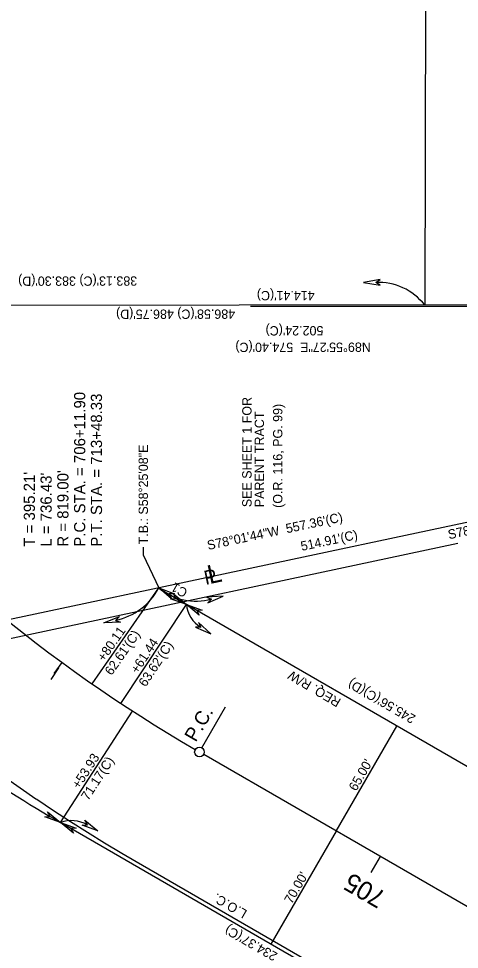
# Model space of a CAD drawing. Extents: x 2003883 to 2008298, y 399149 to 424047.
# Drawn here: x 2006208 to 2006444.4, y 402845.4 to 403344.2 of the extents above; entities that cross this region are included whole.
import ezdxf

# ---------------------------------------------------------------- set-up
doc = ezdxf.new("R2010")
doc.units = 0
for name, color, linetype in [('BaselineSurvey', 7, 'Continuous'), ('BaselineTextWt1', 7, 'Continuous'), ('BaselineTextWt2', 7, 'Continuous'), ('ConstLimits', 7, 'Continuous'), ('ConstLimitsText', 7, 'Continuous'), ('EaseLine_ep', 7, 'Continuous'), ('PropertyLine_ep', 7, 'Continuous'), ('PropertyLineSymbol_ep', 7, 'Continuous'), ('PropertyLineText_ep', 7, 'Continuous'), ('RWandLA_StaTie', 7, 'Continuous'), ('RWandLA_Text', 7, 'Continuous'), ('RWandLA_WidthArrow', 7, 'Continuous'), ('RWLine', 7, 'Continuous')]:
    doc.layers.add(name, color=color, linetype=linetype)

msp = doc.modelspace()

# ---------------------------------------------------------------- linework, layer by layer
at = {"layer": 'BaselineSurvey'}
for p, q in [((2006231.22, 402999.2), (2006226.79, 402993.14)), ((2006229.38, 402996.29), (2006225.24, 402990.04)), ((2006229.38, 402996.29), (2006225.24, 402990.04)), ((2006832.62, 402646.39), (2006307.25, 402949.82)), ((2006401.9, 402895.16), (2006396.89, 402886.5))]:
    msp.add_line(p, q, dxfattribs=at)
msp.add_circle((2006305, 402951.12), 2.6, dxfattribs=at)
msp.add_arc((2006714.61, 403660.33), 819, 220.6437, 239.80922, dxfattribs=at)
at = {"layer": 'BaselineTextWt2'}
msp.add_line((2006306.3, 402953.37), (2006318.98, 402975.33), dxfattribs=at)
at = {"layer": 'ConstLimits'}
for points in [[(2006479.85, 403190), (2006332.39, 403189.92)], [(2006560.75, 402724.93), (2006271.01, 402892.27), (2006263.43, 402896.7), (2006254.14, 402902.26), (2006244.92, 402907.94), (2006235.77, 402913.73), (2006226.69, 402919.64), (2006217.68, 402925.65), (2006217.32, 402925.89), (2006217.23, 402925.95), (2006208.75, 402931.77), (2006199.89, 402938), (2006191.11, 402944.34), (2006182.4, 402950.79), (2006173.78, 402957.34), (2006165.23, 402963.99), (2006156.77, 402970.75), (2006148.39, 402977.62), (2006144.25, 402981.1)]]:
    msp.add_lwpolyline(points, dxfattribs=at)
at = {"layer": 'EaseLine_ep'}
msp.add_line((2006443.58, 403062.83), (2006135.87, 402997.59), dxfattribs=at)
at = {"layer": 'PropertyLine_ep'}
for p, q in [((2006426.99, 403705.03), (2006425.79, 403190.74)), ((2006629, 403112.41), (2006166.22, 403014.29))]:
    msp.add_line(p, q, dxfattribs=at)
at = {"layer": 'PropertyLineText_ep'}
for p, q in [((2006401.92, 403204.31), (2006393.02, 403202.81)), ((2006393.05, 403202.82), (2006401.95, 403201.27)), ((2006399.55, 403202.82), (2006401.95, 403204.32)), ((2006401.95, 403201.27), (2006399.55, 403202.82)), ((2006317.75, 403034.6), (2006308.73, 403034.13)), ((2006308.73, 403034.13), (2006311.41, 403033.15)), ((2006311.41, 403033.15), (2006309.41, 403031.15)), ((2006309.43, 403031.17), (2006317.77, 403034.62)), ((2006253.69, 403020.36), (2006262.02, 403023.74)), ((2006262.02, 403023.74), (2006260, 403021.72)), ((2006260, 403021.72), (2006262.67, 403020.71)), ((2006262.67, 403020.71), (2006253.69, 403020.36))]:
    msp.add_line(p, q, dxfattribs=at)
for centre, radius, start, end in [((2006400.86, 403171.13), 31.72, 38.1943, 92.3877), ((2006253.03, 403055.12), 34.11, 281.8454, 331.9543), ((2006303.07, 403063.76), 31.72, 231.0711, 285.2644)]:
    msp.add_arc(centre, radius, start, end, dxfattribs=at)
at = {"layer": 'RWandLA_StaTie'}
for p, q in [((2006247.42, 402987.65), (2006283.14, 403039.08)), ((2006262.88, 402977.18), (2006297.96, 403030.25)), ((2006230.45, 402913.34), (2006269.16, 402973.07))]:
    msp.add_line(p, q, dxfattribs=at)
at = {"layer": 'RWandLA_Text'}
for p, q in [((2006290.03, 403033.31), (2006283.14, 403039.08)), ((2006283.14, 403039.08), (2006291.58, 403036)), ((2006291.58, 403036), (2006288.72, 403035.86)), ((2006288.72, 403035.86), (2006290.03, 403033.31)), ((2006289.53, 403033.33), (2006292.38, 403033.47)), ((2006297.96, 403030.25), (2006289.53, 403033.33)), ((2006291.08, 403036.01), (2006297.96, 403030.25)), ((2006292.38, 403033.47), (2006291.08, 403036.01)), ((2006304.85, 403024.48), (2006297.96, 403030.25)), ((2006297.96, 403030.25), (2006306.4, 403027.16)), ((2006306.4, 403027.16), (2006303.55, 403027.02)), ((2006303.55, 403027.02), (2006304.85, 403024.48)), ((2006305.64, 403018.03), (2006302.81, 403018.08)), ((2006302.83, 403018.08), (2006311.11, 403014.47)), ((2006311.08, 403014.48), (2006304.47, 403020.63)), ((2006304.47, 403020.63), (2006305.64, 403018.03)), ((2006223.56, 402919.11), (2006230.45, 402913.34)), ((2006224.86, 402916.57), (2006223.56, 402919.11)), ((2006222.01, 402916.43), (2006224.86, 402916.57)), ((2006230.45, 402913.34), (2006222.01, 402916.43)), ((2006237.34, 402907.57), (2006230.45, 402913.34)), ((2006230.45, 402913.34), (2006238.89, 402910.26)), ((2006242.06, 402911.93), (2006244.91, 402912.09)), ((2006250.52, 402908.91), (2006242.06, 402911.93)), ((2006243.59, 402914.63), (2006250.52, 402908.91)), ((2006244.91, 402912.09), (2006243.59, 402914.63)), ((2006238.89, 402910.26), (2006236.03, 402910.12)), ((2006236.03, 402910.12), (2006237.34, 402907.57))]:
    msp.add_line(p, q, dxfattribs=at)
msp.add_lwpolyline([(2006274.88, 403060.93), (2006274.88, 403056.86), (2006283.14, 403039.08)], dxfattribs=at)
for centre, radius, start, end in [((2006313.76, 403031.66), 15.86, 185.108, 239.3013), ((2006236.34, 402897.34), 17.06, 60.098, 110.2069)]:
    msp.add_arc(centre, radius, start, end, dxfattribs=at)
at = {"layer": 'RWandLA_WidthArrow'}
for q in [(2006410.85, 402965.05), (2006343.33, 402848.15)]:
    msp.add_line((2006378.34, 402908.76), q, dxfattribs=at)
at = {"layer": 'RWLine'}
for p, q in [((2006617.07, 403190.99), (2006114.83, 403190.33)), ((2006510.61, 402907.43), (2006297.96, 403030.25)), ((2006672.56, 402657.99), (2006230.45, 402913.34))]:
    msp.add_line(p, q, dxfattribs=at)
for radius, start, end in [(629, 238.41878, 239.99111), (764, 230.84944, 239.99112)]:
    msp.add_arc((2006612.55, 403574.93), radius, start, end, dxfattribs=at)

# ---------------------------------------------------------------- texts
at = {"layer": 'BaselineTextWt1'}
for s, p in [('P.C. STA. = 706+11.90', (2006243.73, 403061.19)), ('P.T. STA. = 713+48.33', (2006252.73, 403061.19)), ("R = 819.00'", (2006234.73, 403061.19)), ("T = 395.21'", (2006216.73, 403061.19)), ("L = 736.43'", (2006225.73, 403061.19))]:
    msp.add_text(s, height=6, rotation=90, dxfattribs=at).set_placement(p)
at = {"layer": 'BaselineTextWt2'}
for s, height, rotation, p in [('P.C.', 7.5, 59.9911, (2006302.98, 402956.08)), ('705', 10, 149.9911, (2006405.73, 402875.62))]:
    msp.add_text(s, height=height, rotation=rotation, dxfattribs=at).set_placement(p)
at = {"layer": 'ConstLimitsText'}
msp.add_text('L.O.C.', height=5, rotation=149.9902, dxfattribs=at).set_placement((2006330.98, 402866.02))
at = {"layer": 'PropertyLineSymbol_ep'}
for s, height, p in [('L', 10, (2006310.39, 403041.13)), ('P', 7.5, (2006308.32, 403040.74))]:
    msp.add_text(s, height=height, rotation=11.9711, dxfattribs=at).set_placement(p)
at = {"layer": 'PropertyLineText_ep'}
for s, rotation, p in [("383.13'(C) 383.30'(D)", 180.0758, (2006271.6, 403206.07)), ("414.41'(C)", 180.0758, (2006366.79, 403198.28)), ("486.58'(C) 486.75'(D)", 180.0758, (2006324.12, 403188.33)), ('SEE SHEET 1 FOR', 90, (2006332.93, 403082.36)), ('(O.R. 116, PG. 99)', 90, (2006349.47, 403082)), ('PARENT TRACT', 90, (2006339.61, 403082.36)), ('S78°01\'44"W  934.02\'(C) 932.92\'(D)', 11.9711, (2006438.84, 403065.17)), ("514.91'(C)", 11.9711, (2006359.88, 403058.91))]:
    msp.add_text(s, height=5, rotation=rotation, dxfattribs=at).set_placement(p)
at = {"layer": 'RWandLA_Text'}
for s, rotation, p in [("502.24'(C)", 180.0758, (2006371.46, 403179.42)), ('N89°55\'27"E  574.40\'(C)', 180.0758, (2006396.9, 403170.61)), ('T.B.: S58°25\'08"E', 90, (2006277.36, 403062.4)), ('S78°01\'44"W  557.36\'(C)', 11.9711, (2006309.69, 403059.41)), ('C1', 149.4178, (2006299.11, 403037.9)), ('+80.11', 55.2192, (2006253.87, 402999.22)), ("62.61'(C)", 55.2192, (2006257.89, 402991.85)), ('+61.44', 56.5254, (2006271.81, 402992.76)), ("63.62'(C)", 56.5254, (2006276.12, 402985.69)), ('REQ. R/W', 149.6285, (2006381.31, 402979.26)), ("245.56'(C)(D)", 149.9911, (2006421.39, 402970.41)), ('+53.93', 57.0507, (2006240.4, 402930.99)), ('71.17(C)', 57.0507, (2006245.31, 402924.79)), ("65.00'", 59.9911, (2006389.05, 402929.83)), ("70.00'", 59.9911, (2006354.48, 402869.41)), ("234.37'(C)", 149.9911, (2006347.3, 402843.12))]:
    msp.add_text(s, height=5, rotation=rotation, dxfattribs=at).set_placement(p)

doc.saveas('drawing.dxf')
